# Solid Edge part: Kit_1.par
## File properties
Author: bmolnar
Last saved by: bmolnar
Revision: 76
Sűrűség: 0,000 kg/m^3
Pontosság: 0,990
Username: bmolnar
Dokumentum tartalom típus: 0
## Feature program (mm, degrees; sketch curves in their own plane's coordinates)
base feature "unnamed BaseFeature 1"
sketch for "Furat_1" plane through (-20.15, 0, 96.65) normal (1, 0, 0) x-axis (0, 1, 0)
  hole centre (0, -15.15) bore radius 2.067
hole "Furat_1" nominal diameter 5 finite  ThreadDepth = 5 mm; StartChamferOffset = 0.6 mm; StartChamferAngle = 45 deg
sketch for "Furat_2" plane through (-13, -13, 83.9) normal (0, 0, 1) x-axis (0, 1, 0)
  hole centre (0, 0) bore radius 2.067
hole "Furat_2" nominal diameter 5
sketch for "unnamed Hole 1" plane through (-13, -13, 83.9) normal (0, 0, 1) x-axis (0, 1, 0)
  hole centre (26, 0) bore radius 2.067
hole "unnamed Hole 1"
sketch for "unnamed Hole 2" plane through (-13, -13, 83.9) normal (0, 0, 1) x-axis (0, 1, 0)
  hole centre (26, -26) bore radius 2.067
hole "unnamed Hole 2"
sketch for "unnamed Hole 3" plane through (-13, -13, 83.9) normal (0, 0, 1) x-axis (0, 1, 0)
  hole centre (0, -26) bore radius 2.067
hole "unnamed Hole 3"
pattern "unnamed Pattern 1" of "Furat_2", "unnamed Hole 1", "unnamed Hole 2", "unnamed Hole 3"
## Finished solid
Body 1: solid body, 265 faces, 630 edges, 376 vertices, 3 internal voids.
  Faces by surface: plane 132, cylinder 56, swept 42, cone 26, torus 9
  Edges by curve: line 381, circle 155, spline 88, curve on surface 5, ellipse 1
Bounding box of the edges (mm; curved faces can reach further): 40.300 x 40.300 x 12.500, from (-20.15, -20.15, 76.5) to (20.15, 20.15, 89).
Cylindrical faces by radius (mm): R0.2 x18, R0.4246 x1, R0.4865 x1, R2.067 x5, R3.75 x2, R4 x4, R4.1 x12, R5.24 x1, R5.45 x2, R5.55 x2, R5.7 x1, R6 x1, R6.92 x1, R7 x1, R13.75 x4
Conical faces (half-angle, radius in mm at the cone's reference point): 0.5 deg R5 x4, 3 deg R6.96 x1, 7 deg R6.4156 x1, 14 deg R5.12 x1, 14 deg R5.3801 x1, 17 deg R5.12 x1, 23 deg R5.7369 x1, 42.5 deg R5.1096 x1, 45 deg R2.317 x2, 45 deg R2.367 x2, 45 deg R2.667 x1, 45 deg R4.25 x2, 45 deg R5.3 x2, 45 deg R5.35 x2, 45 deg R5.85 x1, 84 deg R5.4096 x1, 85 deg R6.73 x1, 87 deg R5.1371 x1
Toroidal faces (ring radius, tube radius in mm): R3.8 r0.2 x2, R4.4 r0.4 x2, R5.6606 r0.18 x1, R6.1131 r0.26 x1, R6.72 r0.2 x1, R9.4957 r0.5 x1, R11.0043 r0.5 x1
Planar faces by outward normal: +x 5, +y 16, +z 17, -x 7, -y 13, -z 5, oblique 69
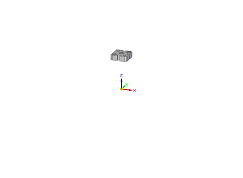
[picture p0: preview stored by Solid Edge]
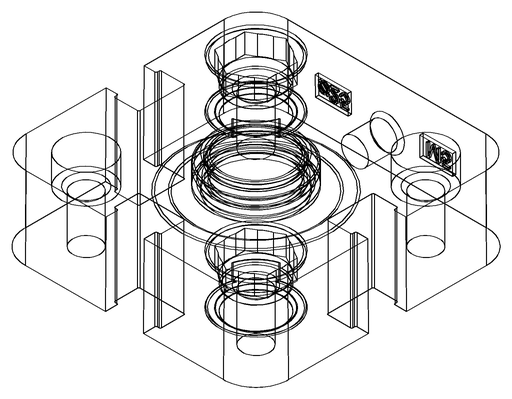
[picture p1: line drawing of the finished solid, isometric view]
